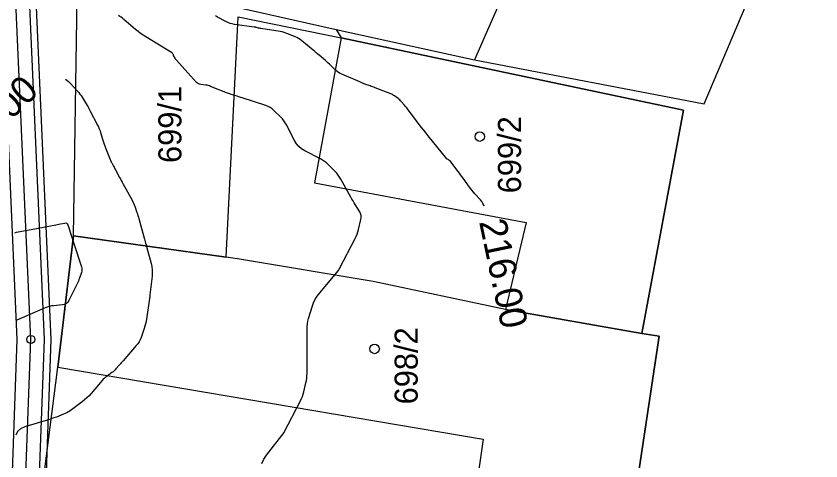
# Model space of a CAD drawing. Extents: x -534481 to -534262, y -1190577 to -1190138.
# Drawn here: x -534409.62 to -534379.97, y -1190413.9 to -1190397.49 of the extents above; entities that cross this region are included whole.
import ezdxf

# ---------------------------------------------------------------- set-up
doc = ezdxf.new("R2010")
doc.units = 0
for name, color, linetype in [('Bonity', 7, 'Continuous'), ('Definiční body', 7, 'Continuous'), ('Polygon budovy', 7, 'Continuous'), ('Polygon parcely', 7, 'Continuous'), ('Vrstva 17', 7, 'Continuous'), ('Vrstva 18', 7, 'Continuous'), ('Vrstva 19', 7, 'Continuous'), ('Vrstva 35', 7, 'Continuous'), ('Vrstva 37', 7, 'Continuous'), ('Vrstva 46', 7, 'Continuous')]:
    doc.layers.add(name, color=color, linetype=linetype)

msp = doc.modelspace()

# ---------------------------------------------------------------- linework, layer by layer
at = {"layer": 'Bonity'}
msp.add_lwpolyline([(-534408.105, -1190518.46), (-534393.616, -1190502.389), (-534391.346, -1190496.962), (-534392.763, -1190488.017), (-534396.655, -1190477.752), (-534402.513, -1190464.283), (-534404.757, -1190456.741), (-534408.311, -1190433.088), (-534409.248, -1190427.879), (-534409.316, -1190416.054), (-534409.076, -1190409.418), (-534409.868, -1190391.439)], dxfattribs=at)
at = {"layer": 'Definiční body'}
for p, q in [((-534407.5, -1190405.6), (-534407.36, -1190395.83)), ((-534407.36, -1190395.83), (-534397.83, -1190397.99)), ((-534397.83, -1190397.99), (-534397.64, -1190398.3)), ((-534407.5, -1190405.6), (-534401.88, -1190406.38))]:
    msp.add_line(p, q, dxfattribs=at)
for points in [[(-534397.83, -1190397.99), (-534392.73, -1190399.11), (-534384.27, -1190400.73), (-534379.97, -1190390.57)], [(-534401.88, -1190406.38), (-534401.44, -1190397.52), (-534397.64, -1190398.3)], [(-534397.64, -1190398.3), (-534385.03, -1190400.96), (-534386.57, -1190409.2)], [(-534408.57, -1190414.29), (-534408.08, -1190410.44), (-534407.5, -1190405.6)], [(-534386.57, -1190409.2), (-534391.59, -1190408.31), (-534396.47, -1190407.28), (-534401.46, -1190406.44), (-534401.88, -1190406.38)], [(-534386.57, -1190409.2), (-534385.93, -1190409.3), (-534387.24, -1190418.04)]]:
    msp.add_lwpolyline(points, dxfattribs=at)
at = {"layer": 'Polygon parcely'}
for points in [[(-534392.73, -1190399.11), (-534384.27, -1190400.73), (-534379.97, -1190390.57), (-534392.22, -1190385.07), (-534395.24, -1190392.02), (-534390.48, -1190393.97)], [(-534397.64, -1190398.3), (-534398.63, -1190403.64), (-534390.83, -1190405.11), (-534391.59, -1190408.31), (-534386.57, -1190409.2), (-534385.03, -1190400.96)], [(-534407.5, -1190405.6), (-534408.08, -1190410.44), (-534392.41, -1190413.1), (-534392.96, -1190416.94), (-534387.24, -1190418.04), (-534385.93, -1190409.3), (-534386.57, -1190409.2), (-534391.59, -1190408.31), (-534396.47, -1190407.28), (-534401.46, -1190406.44), (-534401.88, -1190406.38)]]:
    msp.add_lwpolyline(points, close=True, dxfattribs=at)
at = {"layer": 'Vrstva 18'}
for points in [[(-534400.561, -1190413.99), (-534400.493, -1190413.835), (-534400.398, -1190413.69), (-534399.744, -1190412.847), (-534399.74, -1190412.841), (-534399.142, -1190411.681), (-534399.105, -1190411.602), (-534399.072, -1190411.522), (-534399.044, -1190411.439), (-534399.022, -1190411.355), (-534398.941, -1190411.015), (-534398.923, -1190410.929), (-534398.911, -1190410.843), (-534398.903, -1190410.757), (-534398.901, -1190410.67), (-534398.901, -1190409.055), (-534398.897, -1190408.95), (-534398.886, -1190408.847), (-534398.867, -1190408.744), (-534398.841, -1190408.643), (-534398.702, -1190408.175), (-534398.664, -1190408.066), (-534398.616, -1190407.962), (-534398.557, -1190407.864), (-534398.488, -1190407.772), (-534397.746, -1190406.872), (-534397.743, -1190406.868), (-534397.739, -1190406.866), (-534397.732, -1190406.861), (-534397.729, -1190406.859), (-534397.727, -1190406.855), (-534397.721, -1190406.844), (-534397.72, -1190406.841), (-534397.711, -1190406.818), (-534397.707, -1190406.809), (-534397.703, -1190406.8), (-534397.129, -1190405.701), (-534397.09, -1190405.62), (-534397.056, -1190405.538), (-534397.027, -1190405.454), (-534397.004, -1190405.367), (-534396.914, -1190404.997), (-534396.903, -1190404.922), (-534396.907, -1190404.849), (-534396.926, -1190404.779), (-534396.96, -1190404.71), (-534397.124, -1190404.442), (-534397.165, -1190404.375), (-534397.205, -1190404.307), (-534397.245, -1190404.239), (-534397.284, -1190404.171), (-534397.656, -1190403.503), (-534397.702, -1190403.428), (-534397.753, -1190403.355), (-534397.808, -1190403.287), (-534397.869, -1190403.222), (-534398.121, -1190402.97), (-534398.186, -1190402.91), (-534398.255, -1190402.855), (-534398.328, -1190402.806), (-534398.405, -1190402.762), (-534398.985, -1190402.461), (-534399.101, -1190402.39), (-534399.202, -1190402.303), (-534399.288, -1190402.203), (-534399.36, -1190402.087), (-534399.661, -1190401.506), (-534399.705, -1190401.429), (-534399.754, -1190401.356), (-534399.809, -1190401.287), (-534399.869, -1190401.222), (-534400.121, -1190400.97), (-534400.186, -1190400.912), (-534400.258, -1190400.862), (-534400.334, -1190400.822), (-534400.416, -1190400.79), (-534401.288, -1190400.51), (-534401.334, -1190400.495), (-534401.379, -1190400.481), (-534401.425, -1190400.466), (-534401.47, -1190400.452), (-534401.652, -1190400.394), (-534401.697, -1190400.38), (-534401.743, -1190400.364), (-534401.787, -1190400.348), (-534401.832, -1190400.33), (-534402.451, -1190400.084), (-534402.495, -1190400.069), (-534402.539, -1190400.056), (-534402.584, -1190400.046), (-534402.63, -1190400.04), (-534402.814, -1190400.019), (-534402.859, -1190400.01), (-534402.899, -1190399.994), (-534402.936, -1190399.97), (-534402.969, -1190399.939), (-534403.713, -1190399.119), (-534403.727, -1190399.102), (-534403.741, -1190399.084), (-534403.753, -1190399.065), (-534403.764, -1190399.046), (-534403.814, -1190398.947), (-534403.825, -1190398.926), (-534403.836, -1190398.906), (-534403.858, -1190398.865), (-534403.864, -1190398.855), (-534403.872, -1190398.847), (-534403.88, -1190398.839), (-534403.889, -1190398.833), (-534404.84, -1190398.261), (-534404.938, -1190398.199), (-534405.034, -1190398.133), (-534405.126, -1190398.063), (-534405.215, -1190397.989), (-534405.648, -1190397.616), (-534405.696, -1190397.576), (-534405.747, -1190397.539), (-534405.799, -1190397.504), (-534405.852, -1190397.471)], [(-534409.671, -1190405.482), (-534409.608, -1190405.463), (-534409.27, -1190405.398), (-534409.134, -1190405.373), (-534409.067, -1190405.36), (-534408.151, -1190405.186), (-534407.988, -1190405.155), (-534407.825, -1190405.124), (-534407.787, -1190405.123), (-534407.757, -1190405.133), (-534407.734, -1190405.154), (-534407.717, -1190405.188), (-534407.28, -1190406.523), (-534407.209, -1190406.739), (-534407.196, -1190406.791), (-534407.192, -1190406.844), (-534407.197, -1190406.897), (-534407.211, -1190406.95), (-534407.285, -1190407.16), (-534407.305, -1190407.212), (-534407.325, -1190407.264), (-534407.348, -1190407.315), (-534407.371, -1190407.365), (-534407.671, -1190407.977), (-534407.713, -1190408.043), (-534407.766, -1190408.092), (-534407.831, -1190408.125), (-534407.907, -1190408.141), (-534408.235, -1190408.173), (-534408.316, -1190408.184), (-534408.396, -1190408.201), (-534408.474, -1190408.225), (-534408.55, -1190408.255), (-534409.595, -1190408.712), (-534409.609, -1190408.718), (-534409.623, -1190408.723)]]:
    msp.add_lwpolyline(points, dxfattribs=at)
at = {"layer": 'Vrstva 19'}
for points in [[(-534392.381, -1190404.507), (-534392.392, -1190404.47), (-534392.421, -1190404.4), (-534392.46, -1190404.335), (-534392.509, -1190404.275), (-534392.72, -1190404.043), (-534392.771, -1190403.984), (-534392.822, -1190403.924), (-534392.87, -1190403.862), (-534392.917, -1190403.799), (-534393.15, -1190403.473), (-534393.196, -1190403.41), (-534393.242, -1190403.347), (-534393.288, -1190403.284), (-534393.335, -1190403.221), (-534393.6, -1190402.863), (-534393.608, -1190402.854), (-534393.616, -1190402.846), (-534393.625, -1190402.839), (-534393.634, -1190402.832), (-534393.682, -1190402.802), (-534393.694, -1190402.795), (-534393.706, -1190402.788), (-534393.731, -1190402.775), (-534393.737, -1190402.772), (-534393.742, -1190402.767), (-534393.747, -1190402.763), (-534393.752, -1190402.758), (-534394.433, -1190401.914), (-534394.517, -1190401.808), (-534394.601, -1190401.703), (-534394.684, -1190401.596), (-534394.766, -1190401.489), (-534395.203, -1190400.913), (-534395.23, -1190400.879), (-534395.257, -1190400.845), (-534395.284, -1190400.812), (-534395.312, -1190400.779), (-534395.428, -1190400.644), (-534395.455, -1190400.614), (-534395.484, -1190400.586), (-534395.514, -1190400.559), (-534395.546, -1190400.535), (-534395.678, -1190400.44), (-534395.711, -1190400.417), (-534395.746, -1190400.397), (-534395.781, -1190400.378), (-534395.819, -1190400.362), (-534396.394, -1190400.137), (-534396.44, -1190400.119), (-534396.487, -1190400.101), (-534396.534, -1190400.084), (-534396.581, -1190400.066), (-534396.768, -1190399.998), (-534396.815, -1190399.98), (-534396.861, -1190399.962), (-534396.908, -1190399.943), (-534396.954, -1190399.924), (-534397.622, -1190399.64), (-534397.681, -1190399.612), (-534397.736, -1190399.579), (-534397.789, -1190399.541), (-534397.838, -1190399.497), (-534398.027, -1190399.315), (-534398.075, -1190399.269), (-534398.123, -1190399.225), (-534398.172, -1190399.181), (-534398.221, -1190399.137), (-534398.451, -1190398.939), (-534398.506, -1190398.892), (-534398.561, -1190398.845), (-534398.616, -1190398.798), (-534398.672, -1190398.752), (-534399.095, -1190398.401), (-534399.152, -1190398.357), (-534399.212, -1190398.318), (-534399.275, -1190398.283), (-534399.341, -1190398.253), (-534399.609, -1190398.143), (-534399.677, -1190398.117), (-534399.745, -1190398.095), (-534399.815, -1190398.078), (-534399.886, -1190398.064), (-534400.606, -1190397.948), (-534400.626, -1190397.945), (-534400.646, -1190397.941), (-534400.666, -1190397.937), (-534400.686, -1190397.933), (-534400.765, -1190397.915), (-534400.785, -1190397.91), (-534400.804, -1190397.907), (-534400.824, -1190397.903), (-534400.844, -1190397.9), (-534401.573, -1190397.799), (-534401.657, -1190397.784), (-534401.738, -1190397.761), (-534401.817, -1190397.731), (-534401.894, -1190397.694), (-534402.195, -1190397.53), (-534402.27, -1190397.488)], [(-534407.8, -1190399.822), (-534407.753, -1190399.854), (-534407.685, -1190399.909), (-534407.623, -1190399.971), (-534407.358, -1190400.259), (-534407.311, -1190400.312), (-534407.267, -1190400.367), (-534407.226, -1190400.424), (-534407.188, -1190400.484), (-534407.04, -1190400.724), (-534407.004, -1190400.785), (-534406.968, -1190400.846), (-534406.934, -1190400.907), (-534406.901, -1190400.97), (-534406.614, -1190401.517), (-534406.582, -1190401.583), (-534406.553, -1190401.65), (-534406.526, -1190401.719), (-534406.504, -1190401.789), (-534406.418, -1190402.071), (-534406.396, -1190402.141), (-534406.373, -1190402.211), (-534406.348, -1190402.28), (-534406.322, -1190402.349), (-534406.155, -1190402.778), (-534406.141, -1190402.811), (-534406.127, -1190402.844), (-534406.112, -1190402.876), (-534406.095, -1190402.908), (-534406.029, -1190403.034), (-534406.012, -1190403.066), (-534405.996, -1190403.097), (-534405.979, -1190403.129), (-534405.961, -1190403.16), (-534405.806, -1190403.441), (-534405.775, -1190403.498), (-534405.743, -1190403.555), (-534405.712, -1190403.613), (-534405.681, -1190403.67), (-534405.347, -1190404.286), (-534405.32, -1190404.339), (-534405.294, -1190404.394), (-534405.271, -1190404.449), (-534405.25, -1190404.505), (-534405.17, -1190404.731), (-534405.151, -1190404.788), (-534405.132, -1190404.845), (-534405.115, -1190404.903), (-534405.098, -1190404.96), (-534404.914, -1190405.63), (-534404.889, -1190405.72), (-534404.847, -1190405.872), (-534404.831, -1190405.932), (-534404.814, -1190405.993), (-534404.643, -1190406.616), (-534404.617, -1190406.731), (-534404.603, -1190406.846), (-534404.6, -1190406.962), (-534404.609, -1190407.079), (-534404.694, -1190407.775), (-534404.695, -1190407.786), (-534404.696, -1190407.798), (-534404.696, -1190407.809), (-534404.697, -1190407.82), (-534404.698, -1190407.866), (-534404.699, -1190407.877), (-534404.699, -1190407.889), (-534404.701, -1190407.9), (-534404.702, -1190407.911), (-534404.817, -1190408.67), (-534404.832, -1190408.757), (-534404.851, -1190408.843), (-534404.874, -1190408.928), (-534404.901, -1190409.012), (-534405.016, -1190409.346), (-534405.049, -1190409.428), (-534405.089, -1190409.505), (-534405.136, -1190409.578), (-534405.19, -1190409.647), (-534405.678, -1190410.208), (-534405.711, -1190410.245), (-534405.743, -1190410.283), (-534405.776, -1190410.32), (-534405.809, -1190410.357), (-534405.941, -1190410.506), (-534405.975, -1190410.543), (-534406.01, -1190410.577), (-534406.048, -1190410.609), (-534406.087, -1190410.639), (-534406.279, -1190410.779), (-534406.323, -1190410.813), (-534406.366, -1190410.849), (-534406.405, -1190410.888), (-534406.443, -1190410.929), (-534406.856, -1190411.408), (-534406.933, -1190411.493), (-534407.014, -1190411.573), (-534407.1, -1190411.648), (-534407.19, -1190411.719), (-534407.632, -1190412.049), (-534407.689, -1190412.088), (-534407.748, -1190412.123), (-534407.809, -1190412.154), (-534407.872, -1190412.18), (-534408.13, -1190412.279), (-534408.195, -1190412.303), (-534408.26, -1190412.326), (-534408.325, -1190412.348), (-534408.391, -1190412.369), (-534409.301, -1190412.645), (-534409.454, -1190412.714), (-534409.564, -1190412.815), (-534409.631, -1190412.948)]]:
    msp.add_lwpolyline(points, dxfattribs=at)
at = {"layer": 'Vrstva 35'}
for points in [[(-534405.057, -1190514.333), (-534394.044, -1190502.118), (-534391.862, -1190496.9), (-534393.249, -1190488.146), (-534397.118, -1190477.94), (-534402.983, -1190464.455), (-534405.247, -1190456.85), (-534408.804, -1190433.17), (-534409.748, -1190427.925), (-534409.816, -1190416.046), (-534409.577, -1190409.42), (-534410.397, -1190390.795)], [(-534403.656, -1190514.273), (-534393.187, -1190502.661), (-534390.83, -1190497.024), (-534392.278, -1190487.888), (-534396.191, -1190477.563), (-534402.042, -1190464.111), (-534404.268, -1190456.632), (-534407.818, -1190433.007), (-534408.749, -1190427.833), (-534408.816, -1190416.061), (-534408.576, -1190409.416), (-534409.363, -1190391.537)], [(-534403.306, -1190514.257), (-534392.973, -1190502.796), (-534390.572, -1190497.055), (-534392.035, -1190487.824), (-534395.96, -1190477.469), (-534401.807, -1190464.025), (-534404.023, -1190456.578), (-534407.571, -1190432.966), (-534408.499, -1190427.81), (-534408.566, -1190416.065), (-534408.326, -1190409.415), (-534409.111, -1190391.586)]]:
    msp.add_lwpolyline(points, dxfattribs=at)
at = {"layer": 'Vrstva 37'}
msp.add_circle((-534409.076, -1190409.418), 0.15, dxfattribs=at)
msp.add_circle((-534409.076, -1190409.418), 0.15, dxfattribs=at)
msp.add_circle((-534409.076, -1190409.418), 0.15, dxfattribs=at)
msp.add_circle((-534409.076, -1190409.418), 0.15, dxfattribs=at)
msp.add_circle((-534409.076, -1190409.418), 0.15, dxfattribs=at)
msp.add_circle((-534409.076, -1190409.418), 0.15, dxfattribs=at)
at = {"layer": 'Vrstva 46'}
for centre in [(-534392.536, -1190401.938), (-534396.412, -1190409.769)]:
    msp.add_circle(centre, 0.175, dxfattribs=at)

# ---------------------------------------------------------------- texts
at = {"layer": 'Polygon budovy'}
for s, p in [('699/1', (-534403.529, -1190402.912)), ('699/2', (-534391.017, -1190404.03)), ('698/2', (-534394.824, -1190411.814))]:
    msp.add_text(s, height=0.85, rotation=90, dxfattribs=at).set_placement(p)
at = {"layer": 'Vrstva 17'}
for s, rotation, p in [('215.00', 43.7488, (-534411.684, -1190403.143)), ('216.00', 281.8324, (-534392.566, -1190405.077))]:
    msp.add_text(s, height=1, rotation=rotation, dxfattribs=at).set_placement(p)

doc.saveas('drawing.dxf')
